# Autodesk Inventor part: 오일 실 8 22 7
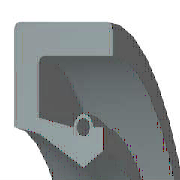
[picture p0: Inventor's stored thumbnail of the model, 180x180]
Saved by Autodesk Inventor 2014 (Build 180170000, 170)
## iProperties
IsCustomPart: 1
Created: 2012-02
Part Number: 오일 실 8 22 7
Material: 고무
Description: 오일-실
Document SubType Name: Modeling
Standard: KS B 2804
Designer: test
Standards Organization: KS
Language: ko-KR
Size Designation: S - 8 22 7
Categories: <MemberInstance><Categories><Category DisplayName="샤프트 부품" InternalName="7f7aeb1f-a693-4053-b835-cee3144e0d98" Mnemonic="SHFT"><Category DisplayName="실링" Intern
Density: 0.93 g/cm^3
Appearance: 고무 - 검은색 - 버전 1.1
Mass: 1.07912 g
Surface Area: 17.6852 cm^2
Volume: 1.16034 cm^3
Author: test
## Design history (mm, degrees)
revolve "본체" stored, may be unused: angle "d17" = 90 deg
revolve "스프링1" stored, may be unused: angle "d18" = 90 deg
body "Solid1"
sketch "스케치1"
  geometry: L1 (0, 11)-(7, 11); L2 (7, 11)-(7, 9.75); L3 (7, 9.75)-(1.75, 9.75); L4 (0, 11)-(0, 6.1); L5 (0, 6.1)-(1.75, 5.75); L6 (1.75, 5.75)-(4.9, 4); L7 (4.9, 4)-(0, 4); L8 (6.3, 4.875)-(6.3, 6.1); L9 (0, 0)-(9.586, 0) reference; L10 (4.9, 4)-(6.3, 4.875); L11 (0, 18)-(0, -3) reference; L12 (-1.917, 0)-(11.503, 0) reference; L13 (4.2, 6.1)-(1.75, 6.59); L14 (1.75, 6.59)-(1.75, 9.75); L15 (6.3, 6.1)-(5.6, 6.1); C1 r 0.455 at (4.9, 6.1); A1 r 0.7 centre (4.9, 6.1) between (5.6, 6.1) and (4.2, 6.1)
  constraints: 26 end point, 5 horizontal alignment, 4 perpendicular, 2 centre point, 2 collinear, 2 horizontal, 2 parallel, 2 point on circle, 2 point on line, 2 vertical alignment, 1 coincident
  dimensions: "d0" = 22 diameter of L1 L9 (= SD2); "d1" = 9.75 diameter of L8.start L9 (= ABDM); "d2" = 1.25 distance of L1.end L2.end (computed from SD); "d3" = 0.91 diameter of C1 (= SPDI); "d4" = 1.4 diameter of A1 (= SPDA); "d5" = 8 diameter of L6.end L9 (= NND); "d6" = 11.5 diameter of L5.end L9 (= TKDM); "d7" = 12.2 diameter of L4.end L9 (= HLDM); "d8" = 4.9 distance from line of C1.centre L4 (= SPDST); "d9" = 6.3 distance between parallel lines of L8 L4 (= SDI); "d10" = 7 distance between parallel lines of L2 L4 (= SWDT); "d12" = 1.75 distance between parallel lines of L14 L4 (= SD)
fillet "모깎기1" dims "d11" = 0.3 (= RR)
other parameters: "SD2" = 22 [user parameter; used in 1 equation term], "SWDT" = 7 [user parameter; used in 1 equation term], "RR" = 0.3 [user parameter; used in 1 equation term], "SD" = 1.75 [user parameter; used in 2 equation terms], "NND" = 8 [user parameter; used in 1 equation term], "SPDA" = 1.4 [user parameter; used in 1 equation term], "SPDI" = 0.91 [user parameter; used in 1 equation term], "TKDM" = 11.5 [user parameter; used in 1 equation term], "HLDM" = 12.2 [user parameter; used in 1 equation term], "ABDM" = 9.75 [user parameter; used in 1 equation term], "SDI" = 6.3 [user parameter; used in 1 equation term], "SPDST" = 4.9 [user parameter; used in 1 equation term], "d13" = 0, "d14" = 0, "d15" = 0, "LAB" = 0.35 [user parameter]
